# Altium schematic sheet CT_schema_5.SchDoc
size 218 x 258 mm
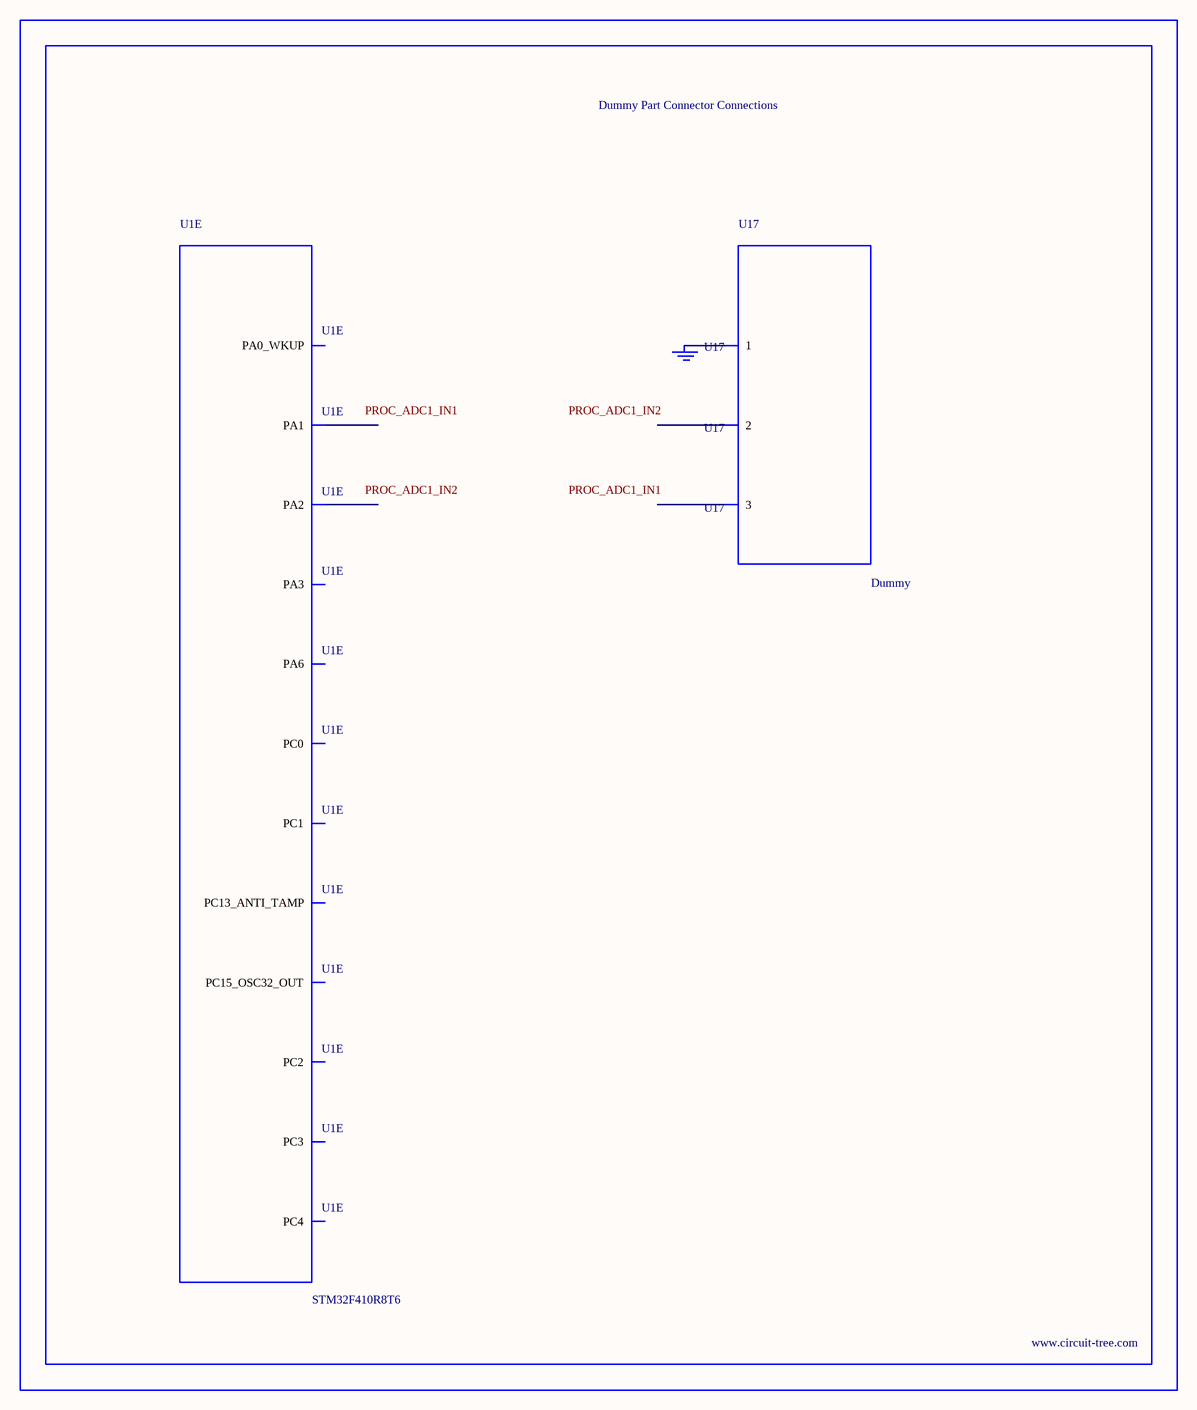
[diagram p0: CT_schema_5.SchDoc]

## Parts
BORDER4  (no value)
GND_INSTANCE_4_0  (no value)
U1  STM32F410R8T6  [LQFP64]  (part E of 5)
U17  Dummy  [DUMMY_PACKAGE_165]

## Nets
NetGND_INSTANCE_4_0_0: GND_INSTANCE_4_0.0(GND) U17.1

Not connected (* = marked no-connect by the designer): U1 2(PC13_ANTI_TAMP) 4(PC15_OSC32_OUT) 8(PC0) 9(PC1) 10(PC2) 11(PC3) 14(PA0_WKUP) 15(PA1) 16(PA2) 17(PA3) 22(PA6) 24(PC4); U17 2 3

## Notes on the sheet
- Labels drawn without touching a wire or pin: PROC_ADC1_IN1, PROC_ADC1_IN2

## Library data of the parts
BORDER4 = BORDER_PAGE4
GND_INSTANCE_4_0 = GND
